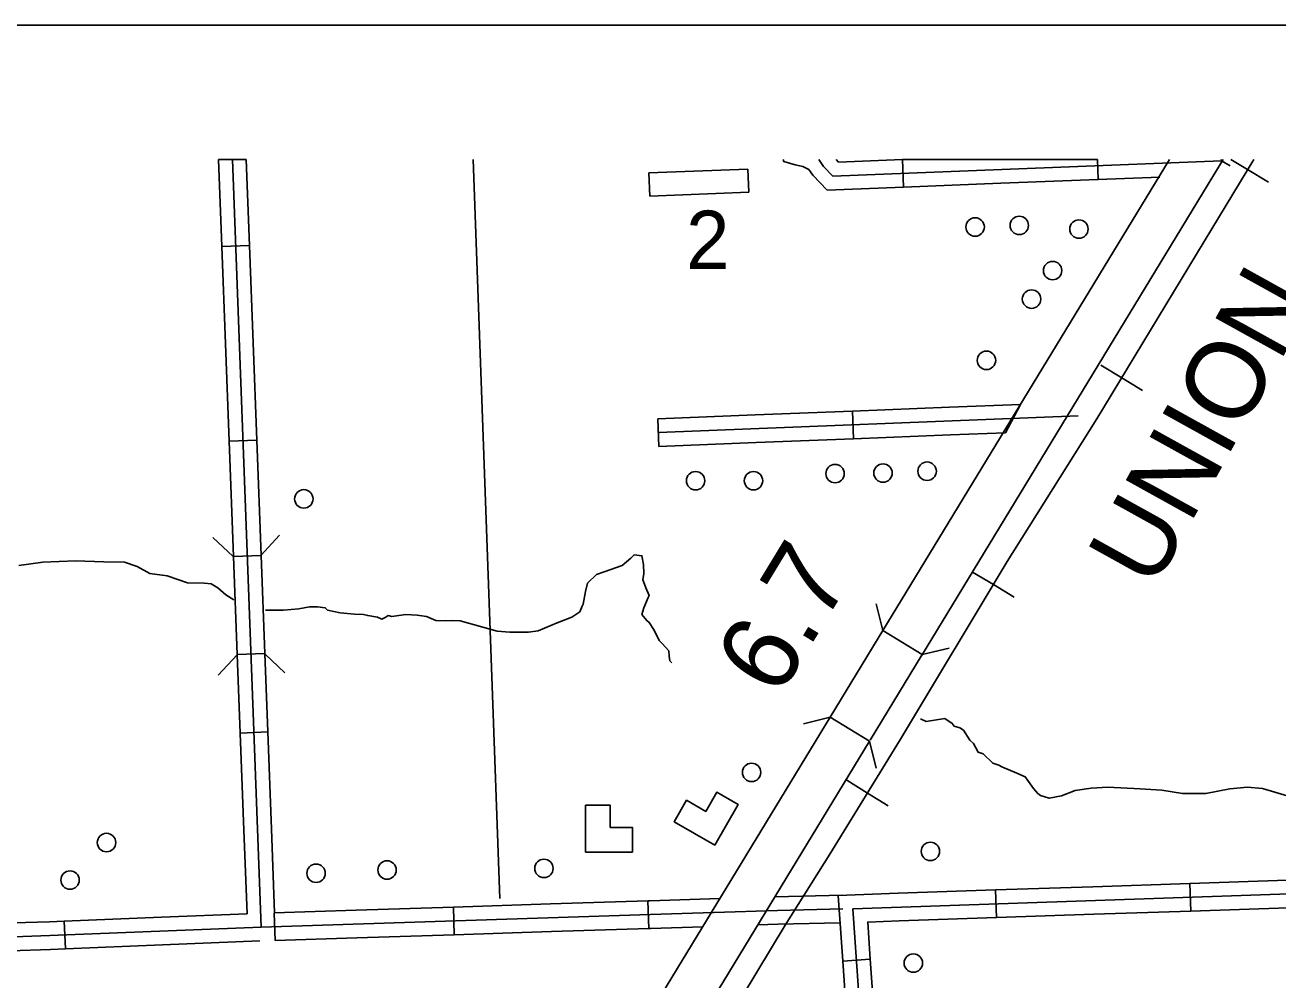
# Model space of a CAD drawing. Extents: x 309348 to 309445, y 336383 to 336484.
# Drawn here: x 309354.217 to 309355.577, y 336402.952 to 336403.988 of the extents above; entities that cross this region are included whole.
import ezdxf

# ---------------------------------------------------------------- set-up
doc = ezdxf.new("R2010")
doc.units = 0
doc.layers.add('R_Annotation', color=7, linetype='Continuous')
doc.layers.add('R_Border Notes', color=7, linetype='Continuous')

msp = doc.modelspace()

# ---------------------------------------------------------------- linework, layer by layer
at = {"layer": 'R_Annotation'}
for p, q in [((309354.4267, 336403.8418), (309354.4302, 336403.7473)), ((309354.4567, 336403.8418), (309354.4267, 336403.8418)), ((309354.4602, 336403.7485), (309354.4567, 336403.8418)), ((309355.0012, 336403.8313), (309354.8937, 336403.8272)), ((309355.0021, 336403.8063), (309355.0012, 336403.8313)), ((309355.1696, 336403.8418), (309355.1692, 336403.8418)), ((309355.1692, 336403.8418), (309355.1703, 336403.8118)), ((309355.3806, 336403.8418), (309355.1696, 336403.8418)), ((309355.3815, 336403.8202), (309355.3806, 336403.8418)), ((309355.5437, 336403.8308), (309355.5254, 336403.8418)), ((309355.5437, 336403.8308), (309355.5664, 336403.8171)), ((309354.8937, 336403.8272), (309354.8947, 336403.8022)), ((309355.1703, 336403.8118), (309355.2759, 336403.816)), ((309355.2759, 336403.816), (309355.3815, 336403.8202)), ((309354.8947, 336403.8022), (309355.0021, 336403.8063)), ((309355.4071, 336403.6048), (309355.3845, 336403.6185)), ((309355.4071, 336403.6048), (309355.4297, 336403.5911)), ((309355.2808, 336403.5454), (309355.2971, 336403.5761)), ((309354.9047, 336403.5305), (309354.9035, 336403.5605)), ((309355.1146, 336403.5689), (309355.1158, 336403.5389)), ((309354.4382, 336403.5362), (309354.4682, 336403.5373)), ((309354.4382, 336403.5362), (309354.4382, 336403.5362)), ((309354.4729, 336403.4123), (309354.4429, 336403.4112)), ((309355.2677, 336403.3805), (309355.2451, 336403.3941)), ((309355.2677, 336403.3805), (309355.2904, 336403.3669)), ((309355.1477, 336403.3306), (309355.1905, 336403.3046)), ((309355.1691, 336403.3176), (309355.1691, 336403.3176)), ((309354.4469, 336403.3046), (309354.4769, 336403.3057)), ((309355.0906, 336403.2366), (309355.1333, 336403.2106)), ((309354.4801, 336403.2207), (309354.4501, 336403.2195)), ((309355.1119, 336403.2236), (309355.1119, 336403.2236)), ((309355.1311, 336403.1544), (309355.1087, 336403.1683)), ((309355.1311, 336403.1544), (309355.1536, 336403.1406)), ((309355.4811, 336403.0564), (309355.4821, 336403.0264)), ((309355.271, 336403.0192), (309355.27, 336403.0492)), ((309354.6815, 336403.0307), (309354.6824, 336403.0007)), ((309354.8936, 336403.0075), (309354.8926, 336403.0375)), ((309354.2591, 336403.0153), (309354.2603, 336402.9853)), ((309354.4882, 336402.9945), (309354.487, 336403.0239)), ((309354.2603, 336402.9853), (309354.2603, 336402.9853)), ((309355.1341, 336402.9741), (309355.1041, 336402.972))]:
    msp.add_line(p, q, dxfattribs=at)
for points in [[(309354.473, 336403.009), (309354.4417, 336403.8418)], [(309354.4418, 336402.0282), (309354.5471, 336402.199), (309354.68, 336402.4155), (309354.7788, 336402.576), (309354.85, 336402.6944), (309354.9335, 336402.8317), (309355.0417, 336403.0111), (309355.0903, 336403.0881), (309355.1659, 336403.2109), (309355.2828, 336403.4055), (309355.3801, 336403.5603), (309355.505, 336403.7665), (309355.5504, 336403.8418)], [(309354.4418, 336402.0282), (309354.5471, 336402.199), (309354.68, 336402.4155), (309354.7788, 336402.576), (309354.85, 336402.6944), (309354.9335, 336402.8317), (309355.0417, 336403.0111), (309355.0903, 336403.0881), (309355.1659, 336403.2109), (309355.2828, 336403.4055), (309355.3801, 336403.5603), (309355.505, 336403.7665), (309355.5504, 336403.8418)], [(309354.7029, 336403.8418), (309354.7319, 336403.04)], [(309355.0396, 336403.8418), (309355.0403, 336403.8396), (309355.0527, 336403.8361), (309355.0609, 336403.8341), (309355.0667, 336403.8312)], [(309355.0667, 336403.8312), (309355.0675, 336403.8308), (309355.0718, 336403.8248), (309355.0873, 336403.8086), (309355.1703, 336403.8118)], [(309355.0781, 336403.8418), (309355.0834, 336403.8344), (309355.0935, 336403.8238), (309355.5153, 336403.8404)], [(309355.097, 336403.8418), (309355.0997, 336403.8391), (309355.1692, 336403.8418)], [(309355.4587, 336403.8418), (309355.1477, 336403.3306)], [(309355.5172, 336403.8418), (309355.1897, 336403.3033)], [(309355.5149, 336403.8418), (309355.5153, 336403.8404), (309355.5247, 336403.8349)], [(309355.3815, 336403.8202), (309355.4482, 336403.8228)], [(309354.4302, 336403.7473), (309354.4602, 336403.7485), (309354.4602, 336403.7485)], [(309354.4342, 336403.6418), (309354.4302, 336403.7473)], [(309354.4642, 336403.6429), (309354.4602, 336403.7485)], [(309354.4382, 336403.5362), (309354.4342, 336403.6418)], [(309354.4682, 336403.5373), (309354.4642, 336403.6429)], [(309355.2201, 336403.5731), (309355.1146, 336403.5689)], [(309355.2971, 336403.5761), (309355.2201, 336403.5731)], [(309354.9035, 336403.5605), (309355.009, 336403.5647)], [(309354.9041, 336403.5455), (309355.3596, 336403.5636)], [(309355.009, 336403.5647), (309355.1146, 336403.5689)], [(309355.2213, 336403.5431), (309355.2808, 336403.5454)], [(309354.4429, 336403.4112), (309354.4382, 336403.5362)], [(309354.4682, 336403.5373), (309354.4729, 336403.4123)], [(309354.9047, 336403.5305), (309355.0102, 336403.5347)], [(309355.0102, 336403.5347), (309355.1158, 336403.5389)], [(309355.1158, 336403.5389), (309355.2213, 336403.5431)], [(309354.4425, 336403.4111), (309354.4205, 336403.4315)], [(309354.4929, 336403.4343), (309354.4725, 336403.4123)], [(309354.4469, 336403.3046), (309354.4429, 336403.4112)], [(309354.4769, 336403.3057), (309354.4729, 336403.4123)], [(309354.4775, 336403.3528), (309354.4972, 336403.3528), (309354.5137, 336403.3544), (309354.5254, 336403.3565), (309354.5339, 336403.3565), (309354.5424, 336403.3554), (309354.545, 336403.3528), (309354.5588, 336403.3501), (309354.5742, 336403.3485), (309354.5838, 336403.348), (309354.5886, 336403.3469), (309354.5992, 336403.3453), (309354.604, 336403.3432), (309354.6083, 336403.3453), (309354.6109, 336403.3469), (309354.6146, 336403.3459), (309354.63, 336403.348), (309354.6423, 336403.3475), (309354.6524, 336403.3459), (309354.6625, 336403.3416), (309354.6726, 336403.3411), (309354.6811, 336403.3416), (309354.689, 336403.3411), (309354.7289, 336403.3299), (309354.7427, 336403.3289), (309354.7528, 336403.3289), (309354.7629, 336403.3289), (309354.7735, 336403.3305), (309354.7942, 336403.339), (309354.8102, 336403.3453), (309354.8187, 336403.3512), (309354.8214, 336403.357), (309354.8224, 336403.3592), (309354.8251, 336403.373), (309354.8272, 336403.382), (309354.8368, 336403.3916), (309354.8453, 336403.3943), (309354.8649, 336403.4012), (309354.874, 336403.4091), (309354.8777, 336403.4129), (309354.8862, 336403.4118), (309354.8878, 336403.4022), (309354.8883, 336403.3927), (309354.8872, 336403.3857), (309354.8899, 336403.3783), (309354.8904, 336403.3772), (309354.8942, 336403.3687), (309354.8931, 336403.3666), (309354.8883, 336403.3554), (309354.8862, 336403.348), (309354.8915, 336403.3416), (309354.8942, 336403.3395), (309354.8989, 336403.3321), (309354.9027, 336403.3246), (309354.9048, 336403.3198), (309354.908, 336403.3166), (309354.9154, 336403.3087), (309354.9159, 336403.3028), (309354.9165, 336403.298), (309354.9188, 336403.2958)], [(309354.2097, 336403.4012), (309354.2357, 336403.4049), (309354.2713, 336403.4065), (309354.3022, 336403.4054), (309354.3245, 336403.4049), (309354.3383, 336403.4001), (309354.3521, 336403.3927), (309354.3707, 336403.39), (309354.393, 336403.3826), (309354.4111, 336403.382), (309354.4185, 336403.3815), (309354.426, 336403.3772), (309354.4345, 336403.3693), (309354.4433, 336403.364)], [(309355.1406, 336403.3598), (309355.1477, 336403.3306)], [(309355.1477, 336403.3306), (309355.0906, 336403.2366)], [(309354.4263, 336403.2823), (309354.4467, 336403.3043)], [(309354.4501, 336403.2195), (309354.4469, 336403.3046)], [(309354.4767, 336403.3054), (309354.4987, 336403.285)], [(309354.4769, 336403.3057), (309354.4801, 336403.2207)], [(309355.1905, 336403.3046), (309355.1338, 336403.2116)], [(309355.1905, 336403.3046), (309355.2196, 336403.3117)], [(309354.8233, 336402.7989), (309354.8924, 336402.9109), (309355.0906, 336403.2366)], [(309355.0906, 336403.2366), (309355.0614, 336403.2295)], [(309355.1886, 336403.2351), (309355.1949, 336403.2321), (309355.2151, 336403.2353), (309355.2231, 336403.23), (309355.2252, 336403.2268), (309355.2311, 336403.2252), (309355.2353, 336403.2226), (309355.2422, 336403.2119), (309355.246, 336403.2082), (309355.2513, 336403.1986), (309355.2566, 336403.197), (309355.2672, 336403.1869), (309355.2736, 336403.1848), (309355.2768, 336403.1827), (309355.2933, 336403.1758), (309355.3023, 336403.1721), (309355.3113, 336403.1593)], [(309354.454, 336403.114), (309354.4501, 336403.2195)], [(309354.484, 336403.1151), (309354.4801, 336403.2207)], [(309355.1333, 336403.2106), (309354.9352, 336402.885), (309354.8659, 336402.7728)], [(309355.1404, 336403.1815), (309355.1333, 336403.2106)], [(309355.3113, 336403.1593), (309355.3161, 336403.154), (309355.3188, 336403.1519), (309355.3283, 336403.1487), (309355.3416, 336403.1513), (309355.3565, 336403.1572), (309355.374, 336403.1598), (309355.3921, 336403.1609), (309355.4272, 336403.1588), (309355.4506, 336403.1577), (309355.4729, 336403.154), (309355.4984, 336403.154), (309355.5244, 336403.1588), (309355.5436, 336403.1609), (309355.56, 336403.1593), (309355.5866, 336403.1513), (309355.6036, 336403.1487), (309355.6328, 336403.1481), (309355.6552, 336403.154), (309355.6647, 336403.1524), (309355.6897, 336403.1423), (309355.7338, 336403.1338), (309355.746, 336403.1354), (309355.7524, 336403.1359)], [(309354.4575, 336403.0234), (309354.454, 336403.114)], [(309354.4874, 336403.0245), (309354.484, 336403.1151)], [(309356.3238, 336403.0769), (309356.0192, 336403.0714), (309356.0078, 336403.0707), (309355.9998, 336403.0671), (309355.9843, 336403.0605), (309355.9792, 336403.0585), (309355.1152, 336403.0289)], [(309355.3755, 336403.0528), (309355.4811, 336403.0564)], [(309355.5867, 336403.06), (309355.4811, 336403.0564)], [(309355.104, 336403.0436), (309355.0307, 336403.0419)], [(309355.1644, 336403.0456), (309355.0992, 336403.0433), (309355.1041, 336402.972)], [(309355.27, 336403.0492), (309355.1644, 336403.0456)], [(309355.27, 336403.0492), (309355.3755, 336403.0528)], [(309354.5759, 336403.0273), (309354.487, 336403.0244)], [(309354.6815, 336403.0307), (309354.5759, 336403.0273)], [(309354.7871, 336403.0341), (309354.6815, 336403.0307)], [(309354.8926, 336403.0375), (309354.7871, 336403.0341)], [(309354.9709, 336403.04), (309354.8948, 336403.0375), (309354.8926, 336403.0375)], [(309355.1043, 336403.0286), (309355.0333, 336403.027), (309354.8953, 336403.0225)], [(309355.1152, 336403.0289), (309355.1315, 336402.7951)], [(309355.5877, 336403.03), (309355.4821, 336403.0264)], [(309354.8953, 336403.0225), (309354.473, 336403.009), (309354.2436, 336402.9997), (309354.2045, 336402.9984), (309353.6822, 336402.974), (309353.6786, 336402.9728), (309353.6736, 336402.9692)], [(309354.2591, 336403.0153), (309354.2431, 336403.0147), (309354.2039, 336403.0134), (309354.1534, 336403.0111)], [(309354.3646, 336403.0196), (309354.2591, 336403.0153)], [(309354.4575, 336403.0234), (309354.3646, 336403.0196)], [(309355.1013, 336403.0135), (309355.0337, 336403.012), (309355.012, 336403.0113)], [(309355.1654, 336403.0156), (309355.1313, 336403.0144), (309355.1341, 336402.9741)], [(309355.271, 336403.0192), (309355.1654, 336403.0156)], [(309355.3766, 336403.0228), (309355.271, 336403.0192)], [(309355.4821, 336403.0264), (309355.3766, 336403.0228)], [(309354.6824, 336403.0007), (309354.5769, 336402.9973)], [(309354.6824, 336403.0007), (309354.788, 336403.0041)], [(309354.788, 336403.0041), (309354.8936, 336403.0075)], [(309354.9523, 336403.0094), (309354.8958, 336403.0075), (309354.8936, 336403.0075)], [(309354.2603, 336402.9853), (309354.3659, 336402.9896)], [(309354.3659, 336402.9896), (309354.4714, 336402.9939)], [(309354.5769, 336402.9973), (309354.4882, 336402.9945)], [(309354.2603, 336402.9853), (309354.2442, 336402.9847), (309354.2005, 336402.9833)], [(309355.1414, 336402.8687), (309355.1341, 336402.9741)], [(309355.1041, 336402.972), (309355.1115, 336402.8666)]]:
    msp.add_lwpolyline(points, dxfattribs=at)
for points in [[(309354.9653, 336403.0979), (309354.9907, 336403.1419), (309354.9675, 336403.1553), (309354.9555, 336403.1345), (309354.9347, 336403.1465), (309354.9213, 336403.1233)], [(309354.825, 336403.0903), (309354.8758, 336403.0903), (309354.8758, 336403.1171), (309354.8518, 336403.1171), (309354.8518, 336403.1411), (309354.825, 336403.1411)]]:
    msp.add_lwpolyline(points, close=True, dxfattribs=at)
for centre in [(309355.2479, 336403.7686), (309355.2958, 336403.7703), (309355.3606, 336403.7663), (309355.332, 336403.7213), (309355.3091, 336403.6903), (309355.2602, 336403.6239), (309354.9444, 336403.4933), (309355.0073, 336403.4933), (309355.0959, 336403.501), (309355.1479, 336403.5016), (309355.1958, 336403.5036), (309354.5192, 336403.4736), (309355.0052, 336403.1768), (309354.305, 336403.1007), (309355.1993, 336403.0911), (309354.7798, 336403.0726), (309354.2654, 336403.06), (309354.5325, 336403.0674), (309354.6095, 336403.0709), (309355.1808, 336402.9699)]:
    msp.add_circle(centre, 0.01, dxfattribs=at)
at = {"layer": 'R_Border Notes'}
msp.add_line((309347.6607, 336403.9877), (309356.3641, 336403.9877), dxfattribs=at)

# ---------------------------------------------------------------- texts
at = {"layer": 'R_Annotation'}
msp.add_text('2', height=0.0634, dxfattribs=at).set_placement((309354.9341, 336403.7229))
for s, rotation, p in [('UNION', 61.0076, (309355.4413, 336403.3735)), ('6.7', 58.6877, (309355.0343, 336403.2562))]:
    msp.add_text(s, height=0.08451, rotation=rotation, dxfattribs=at).set_placement(p)

doc.saveas('drawing.dxf')
